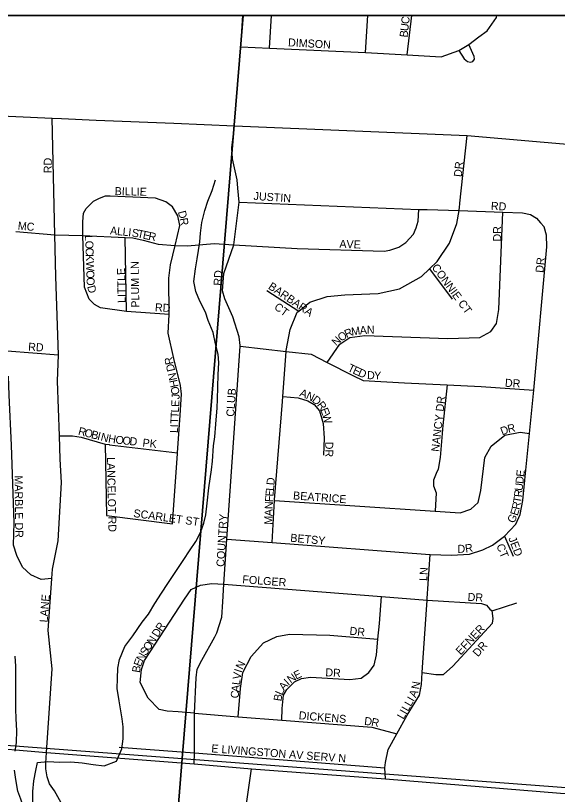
# Model space of a CAD drawing. Extents: x 0 to 34, y 0 to 22.
# Drawn here: x 7.208 to 7.849, y 19.979 to 20.9 of the extents above; entities that cross this region are included whole.
import ezdxf

# ---------------------------------------------------------------- set-up
doc = ezdxf.new("R2010")
doc.units = 0
for name, color, linetype in [('GM_X_City_Street', 7, 'Continuous'), ('GM_X_City_Street_Text', 7, 'Continuous'), ('GM_X_Minor_River', 7, 'Continuous'), ('GM_X_Section', 7, 'Continuous'), ('GM_X_Township', 7, 'Continuous'), ('GM_X_US_Route', 7, 'Continuous'), ('SH_Data', 7, 'Continuous')]:
    doc.layers.add(name, color=color, linetype=linetype)

msp = doc.modelspace()

# ---------------------------------------------------------------- linework, layer by layer
at = {"layer": 'GM_X_City_Street'}
for points in [[(7.46717, 20.77809), (7.47409, 20.86319), (7.47649, 20.9)], [(7.47409, 20.86319), (7.50811, 20.86148), (7.62155, 20.85632), (7.67071, 20.85357), (7.71131, 20.85115), (7.73218, 20.85867), (7.74375, 20.8656), (7.75568, 20.87493), (7.76558, 20.8821), (7.77658, 20.89792), (7.77707, 20.9)], [(7.50811, 20.86148), (7.5105, 20.9)], [(7.62155, 20.85632), (7.62451, 20.9)], [(7.67071, 20.85357), (7.67626, 20.9)], [(7.73218, 20.85867), (7.7385, 20.8487), (7.74222, 20.84559), (7.74598, 20.84475), (7.74866, 20.84583), (7.7506, 20.84845), (7.75028, 20.85149), (7.74375, 20.8656)], [(7.25731, 20.4677), (7.25821, 20.49881), (7.25521, 20.59154), (7.25388, 20.64062), (7.25079, 20.7786)], [(7.41893, 20.0151), (7.41918, 20.0279), (7.41909, 20.07484), (7.4212, 20.11671), (7.42251, 20.12695), (7.42798, 20.13751), (7.44322, 20.16538), (7.44556, 20.16991), (7.45155, 20.18843), (7.45261, 20.20665), (7.45404, 20.22751), (7.45769, 20.28074), (7.47337, 20.50912), (7.47342, 20.50989), (7.47207, 20.52017), (7.46449, 20.54384), (7.45497, 20.56489), (7.45247, 20.57443), (7.45393, 20.59492), (7.46582, 20.62889), (7.47201, 20.67928), (7.47146, 20.68771), (7.47059, 20.69583), (7.46972, 20.70569), (7.46741, 20.71642), (7.46421, 20.73063), (7.46334, 20.74369), (7.46649, 20.7697), (7.46717, 20.77809)], [(7.73323, 20.67817), (7.74188, 20.75814)], [(7.38932, 20.54657), (7.33877, 20.55007), (7.30811, 20.55427), (7.30108, 20.55825), (7.29453, 20.56458), (7.28925, 20.57898), (7.28705, 20.63994), (7.287, 20.65609), (7.28797, 20.66615), (7.29102, 20.67201), (7.29945, 20.67996)], [(7.38932, 20.54657), (7.38886, 20.58939), (7.39097, 20.60521), (7.39635, 20.62801), (7.40173, 20.65164), (7.39962, 20.66312), (7.39307, 20.67388), (7.38547, 20.67962), (7.37294, 20.68418), (7.31958, 20.68628), (7.31349, 20.68628), (7.30658, 20.68371), (7.29945, 20.67996)], [(7.28705, 20.63994), (7.33737, 20.63761), (7.34625, 20.63713), (7.35843, 20.63456), (7.37621, 20.62963), (7.39635, 20.62801), (7.41113, 20.62761), (7.4424, 20.63037), (7.46582, 20.62889), (7.54074, 20.62458), (7.64383, 20.62128), (7.65036, 20.62245), (7.66091, 20.62613), (7.66931, 20.63176), (7.67828, 20.64145), (7.68163, 20.6489), (7.68383, 20.65678), (7.6847, 20.67062)], [(7.47201, 20.67928), (7.6847, 20.67062), (7.69445, 20.67077), (7.73232, 20.66936), (7.7843, 20.66744), (7.80751, 20.66658), (7.81693, 20.66487), (7.82404, 20.66055), (7.82884, 20.65476)], [(7.51111, 20.27668), (7.51393, 20.32647), (7.51398, 20.32719), (7.52349, 20.44352), (7.52391, 20.44955), (7.52766, 20.50281), (7.52773, 20.50378), (7.53239, 20.52873), (7.54073, 20.54906), (7.54255, 20.5505), (7.55572, 20.5609), (7.57626, 20.56769), (7.59709, 20.56954), (7.63644, 20.57139), (7.66189, 20.57694), (7.68788, 20.59122), (7.69732, 20.60032), (7.70639, 20.60905), (7.72081, 20.63077), (7.72959, 20.65413), (7.73232, 20.66936), (7.73258, 20.67076), (7.73265, 20.67276), (7.73323, 20.67817)], [(7.57605, 20.48958), (7.59139, 20.51121), (7.60289, 20.51932), (7.6207, 20.52162), (7.71892, 20.51809), (7.75675, 20.51922), (7.76975, 20.52654), (7.77674, 20.53589), (7.77935, 20.55253), (7.7843, 20.66744)], [(7.78622, 20.28428), (7.79937, 20.29844), (7.80452, 20.31011), (7.80788, 20.32637), (7.81026, 20.35062), (7.81567, 20.40576), (7.82072, 20.45714), (7.83621, 20.62651), (7.83574, 20.64019), (7.83291, 20.65012), (7.82884, 20.65476)], [(7.20767, 20.64479), (7.25388, 20.64062), (7.28705, 20.63994)], [(7.33877, 20.55007), (7.33737, 20.63761)], [(7.69732, 20.60032), (7.72401, 20.56467)], [(7.50496, 20.57484), (7.54255, 20.5505)], [(7.39319, 20.29891), (7.39902, 20.38192), (7.39907, 20.38271), (7.4022, 20.4274), (7.40383, 20.45241), (7.40252, 20.46231), (7.39484, 20.49434), (7.38827, 20.52446), (7.38932, 20.54657)], [(7.04392, 20.49399), (7.06603, 20.5112), (7.07176, 20.51293), (7.08653, 20.51251), (7.19765, 20.50364), (7.25821, 20.49881)], [(7.47337, 20.50912), (7.52766, 20.50281), (7.55713, 20.49938), (7.57605, 20.48958), (7.60652, 20.47447), (7.61888, 20.46852), (7.66759, 20.46562), (7.71822, 20.46311), (7.7586, 20.46111), (7.82072, 20.45714)], [(7.25053, 20.23441), (7.23761, 20.23285), (7.22565, 20.23851), (7.21568, 20.24753), (7.20888, 20.2614), (7.20506, 20.27366), (7.20585, 20.30059), (7.2028, 20.39182), (7.20013, 20.45105), (7.19911, 20.47356)], [(7.24351, 20.01569), (7.24419, 20.02836), (7.25089, 20.12742), (7.24595, 20.17259), (7.25053, 20.23441), (7.25132, 20.24512), (7.2579, 20.27896), (7.26179, 20.34758), (7.26032, 20.37534), (7.25941, 20.40312), (7.25731, 20.4677)], [(7.71822, 20.46311), (7.71308, 20.41535), (7.71005, 20.37746), (7.7075, 20.36347), (7.70514, 20.35859), (7.70195, 20.35068), (7.70219, 20.34384), (7.70505, 20.33543), (7.70396, 20.31402)], [(7.52391, 20.44955), (7.54211, 20.44807), (7.55338, 20.44443), (7.56085, 20.4401), (7.56712, 20.43238), (7.57136, 20.41749), (7.57252, 20.40001), (7.57174, 20.37991)], [(7.51393, 20.32647), (7.70396, 20.31402), (7.73369, 20.31208), (7.74625, 20.31637), (7.7551, 20.32416), (7.75803, 20.33814), (7.76297, 20.37714), (7.77042, 20.39065), (7.78657, 20.40361), (7.80479, 20.40741), (7.81567, 20.40576)], [(7.25941, 20.40312), (7.27507, 20.40305), (7.28524, 20.40132), (7.31336, 20.39317), (7.31846, 20.39254), (7.31875, 20.3925)], [(7.31336, 20.39317), (7.31514, 20.30886)], [(7.31875, 20.3925), (7.39907, 20.38271)], [(7.31514, 20.30886), (7.39319, 20.29891)], [(7.45769, 20.28074), (7.51111, 20.27668), (7.69762, 20.26254), (7.69829, 20.26251), (7.72334, 20.26163), (7.74456, 20.2631), (7.76054, 20.26809), (7.77201, 20.27356), (7.78622, 20.28428)], [(7.78622, 20.28428), (7.79617, 20.2607)], [(7.64519, 19.99722), (7.64455, 20.01026), (7.64534, 20.01667), (7.64829, 20.03179), (7.65853, 20.05058), (7.67104, 20.0727), (7.6855, 20.09632), (7.68802, 20.1088), (7.68873, 20.12321), (7.6893, 20.13496), (7.69447, 20.20848), (7.6946, 20.21039), (7.69829, 20.26251)], [(7.41909, 20.07484), (7.40006, 20.07634), (7.38685, 20.07737), (7.37744, 20.07945), (7.36448, 20.09263), (7.35501, 20.11105), (7.35646, 20.12657), (7.36008, 20.13713), (7.40728, 20.20981), (7.41544, 20.22103), (7.42651, 20.2265), (7.43978, 20.22812), (7.45404, 20.22751)], [(7.45404, 20.22751), (7.64059, 20.21301), (7.69447, 20.20848), (7.75875, 20.20452), (7.76476, 20.2025), (7.76882, 20.19786), (7.77143, 20.19592), (7.80073, 20.20557)], [(7.52271, 20.06672), (7.52301, 20.08066), (7.52445, 20.09619), (7.52837, 20.10295), (7.53763, 20.11187), (7.54602, 20.11587), (7.55664, 20.11755), (7.60308, 20.11471), (7.61635, 20.11633), (7.62556, 20.12298), (7.63178, 20.13158), (7.63467, 20.14405), (7.63636, 20.16258), (7.63807, 20.18118), (7.64059, 20.21301)], [(7.68873, 20.12321), (7.70489, 20.1206), (7.71397, 20.12079), (7.72513, 20.13043), (7.7719, 20.18148), (7.77276, 20.18678), (7.77143, 20.19592)], [(7.47105, 20.07077), (7.47358, 20.10407), (7.47661, 20.12298), (7.48644, 20.14214), (7.50075, 20.15817), (7.51679, 20.16581), (7.53158, 20.16855), (7.57956, 20.16719), (7.63636, 20.16258)], [(7.41909, 20.07484), (7.47105, 20.07077), (7.52271, 20.06672), (7.62917, 20.05837), (7.63669, 20.05632), (7.65853, 20.05058)], [(6.90291, 20.05472), (6.90291, 20.05472), (7.16116, 20.03551), (7.24419, 20.02836), (7.41893, 20.0151), (7.48652, 20.0093)], [(7.33005, 20.03487), (7.41918, 20.0279), (7.64455, 20.01026)], [(7.12805, 19.5971), (7.12788, 19.60303), (7.13529, 19.62004), (7.14308, 19.63744), (7.15701, 19.66048), (7.18874, 19.71372), (7.21392, 19.75791), (7.22441, 19.77908), (7.23406, 19.79341), (7.23776, 19.8047), (7.23878, 19.8078), (7.24239, 19.82525), (7.24469, 19.86056), (7.25022, 19.91334), (7.26132, 19.96893), (7.25357, 19.98307), (7.24776, 19.99142), (7.24479, 19.99976), (7.24315, 20.00899), (7.24351, 20.01569)], [(7.47554, 19.93176), (7.48652, 20.0093)], [(7.48652, 20.0093), (7.64519, 19.99722), (7.8522, 19.98043), (8.03575, 19.96709), (8.08374, 19.96342)]]:
    msp.add_lwpolyline(points, dxfattribs=at)
at = {"layer": 'GM_X_Minor_River'}
for points in [[(7.43161, 20.66966), (7.43509, 20.68065), (7.44008, 20.69314), (7.44394, 20.70564)], [(7.22799, 19.963), (7.22811, 19.98236), (7.22932, 19.99488), (7.23166, 20.00702), (7.23361, 20.01649), (7.24572, 20.01794), (7.2597, 20.0171), (7.27294, 20.01739), (7.28617, 20.01617), (7.29939, 20.0142), (7.31224, 20.0126), (7.32702, 20.0182), (7.33316, 20.03259), (7.33475, 20.04473), (7.33484, 20.05877), (7.33376, 20.06827), (7.33156, 20.08005), (7.33011, 20.08955), (7.32793, 20.10399), (7.328, 20.11613), (7.32846, 20.12828), (7.33041, 20.13852), (7.33693, 20.15366), (7.34646, 20.16651), (7.35715, 20.18239), (7.36477, 20.19221), (7.37241, 20.20469), (7.38005, 20.21679), (7.38769, 20.22851), (7.39799, 20.24363), (7.40677, 20.25686), (7.41326, 20.26707), (7.42089, 20.27803), (7.42625, 20.28863), (7.4301, 20.29961), (7.4328, 20.30946), (7.4344, 20.3235), (7.43603, 20.34133), (7.43956, 20.36256), (7.44038, 20.37318), (7.44163, 20.39102), (7.4432, 20.40163), (7.44443, 20.41681), (7.44606, 20.43616), (7.4465, 20.4464), (7.44697, 20.46044), (7.44744, 20.47562), (7.4479, 20.48928), (7.44721, 20.49953), (7.44426, 20.5117), (7.44131, 20.525), (7.43535, 20.53946), (7.43239, 20.54934), (7.42566, 20.56229), (7.42081, 20.5737), (7.41862, 20.58548), (7.4206, 20.60065), (7.42257, 20.61241), (7.42414, 20.62227), (7.42571, 20.6325), (7.42653, 20.64274), (7.42812, 20.65526), (7.43161, 20.66966)], [(7.20722, 20.02994), (7.20842, 20.04018), (7.20889, 20.05461), (7.20821, 20.06827), (7.20791, 20.08005), (7.20797, 20.08991), (7.20766, 20.10168), (7.20774, 20.11383), (7.20784, 20.13053), (7.20716, 20.14231)], [(7.22822, 19.94989), (7.22035, 19.95128), (7.21702, 19.96345), (7.21368, 19.97334), (7.21034, 19.98285), (7.20777, 19.99653), (7.20633, 20.00755)]]:
    msp.add_lwpolyline(points, dxfattribs=at)
at = {"layer": 'GM_X_Section'}
for p, q in [((7.47668, 20.9), (6.96615, 20.9)), ((7.98444, 20.9), (7.47668, 20.9))]:
    msp.add_line(p, q, dxfattribs=at)
for points in [[(6.96615, 20.9), (6.89954, 20.05948), (7.40469, 20.02134), (7.47668, 20.9)], [(7.47668, 20.9), (7.40469, 20.02134), (7.91105, 19.98299), (7.98444, 20.9)]]:
    msp.add_lwpolyline(points, dxfattribs=at)
for points in [[(6.89954, 20.05948), (7.40469, 20.02134), (7.32396, 19.01244), (6.82179, 19.05189)], [(7.40469, 20.02134), (7.91105, 19.98299), (7.83199, 18.97493), (7.32396, 19.01244)]]:
    msp.add_lwpolyline(points, close=True, dxfattribs=at)
at = {"layer": 'GM_X_Township'}
msp.add_lwpolyline([(9.4, 17.82945), (9.4, 20.9), (4.42993, 20.9)], dxfattribs=at)
at = {"layer": 'GM_X_US_Route'}
for points in [[(6.95519, 20.7898), (7.05834, 20.78049), (7.15585, 20.78303), (7.25079, 20.7786), (7.26185, 20.77814)], [(7.26185, 20.77814), (7.30278, 20.77645)], [(7.30278, 20.77645), (7.39487, 20.77266)], [(7.39487, 20.77266), (7.46649, 20.7697), (7.74188, 20.75814), (7.87401, 20.74661), (7.96446, 20.74516), (8.13798, 20.74238), (8.24345, 20.73449)]]:
    msp.add_lwpolyline(points, dxfattribs=at)
at = {"layer": 'SH_Data'}
msp.add_line((2.6, 20.9), (9.4, 20.9), dxfattribs=at)

# ---------------------------------------------------------------- texts
at = {"layer": 'GM_X_City_Street_Text'}
for s, height, rotation, p in [('C', 0.00947, 83.50034, (7.673, 20.8895)), ('U', 0.00947, 83.49143, (7.67205, 20.88121)), ('B', 0.00947, 83.50156, (7.6712, 20.87376)), ('DIMSON', 0.00947, 356.8796, (7.52974, 20.86367)), ('RD', 0.00947, 90, (7.25037, 20.71356)), ('DR', 0.00947, 83.982, (7.73541, 20.70875)), ('BILLIE', 0.00947, 358.69884, (7.32469, 20.68772)), ('JUSTIN', 0.00947, 356.26572, (7.48893, 20.68201)), ('RD', 0.00947, 356.82219, (7.76975, 20.67034)), ('D', 0.00947, 285.64815, (7.39944, 20.66777)), ('MC', 0.00947, 354.79841, (7.20981, 20.647)), ('R', 0.00947, 279.638, (7.40163, 20.66)), ('A', 0.00947, 354.72443, (7.31897, 20.64117)), ('L', 0.00947, 354.73277, (7.32727, 20.64041)), ('L', 0.00947, 354.75743, (7.33391, 20.63979)), ('I', 0.00947, 353.95437, (7.34052, 20.63919)), ('S', 0.00947, 350.64099, (7.34451, 20.63877)), ('T', 0.00947, 348.19717, (7.35099, 20.6377)), ('E', 0.00947, 348.03116, (7.35751, 20.63634)), ('R', 0.00947, 348.04025, (7.36403, 20.63496)), ('DR', 0.00947, 90, (7.78204, 20.63273)), ('L', 0.00947, 271.8855, (7.28976, 20.64026)), ('AVE', 0.00947, 358.0261, (7.59054, 20.62534)), ('O', 0.00947, 271.90891, (7.28998, 20.6336)), ('C', 0.00947, 271.87032, (7.29026, 20.62527)), ('K', 0.00947, 271.90891, (7.29051, 20.61777)), ('W', 0.00947, 271.88339, (7.29078, 20.60944)), ('PLUM LN', 0.00947, 90.93868, (7.35398, 20.55463)), ('DR', 0.00947, 83.99458, (7.83204, 20.59541)), ('O', 0.00947, 271.88003, (7.29114, 20.59861)), ('LITTLE', 0.00947, 91.21819, (7.33787, 20.56019)), ('RD', 0.00947, 86.81007, (7.4512, 20.58033)), ('CONNIE CT', 0.00947, 306.25242, (7.69942, 20.60211)), ('O', 0.00947, 271.90891, (7.29141, 20.59028)), ('D', 0.00947, 285.65736, (7.29207, 20.5795)), ('BARBARA', 0.00947, 325.83878, (7.50565, 20.57754)), ('RD', 0.00947, 356.98902, (7.37224, 20.55034)), ('CT', 0.00947, 323.74111, (7.51273, 20.55353)), ('A', 0.00947, 5.01235, (7.61515, 20.52291)), ('N', 0.00947, 0.30604, (7.62325, 20.52363)), ('O', 0.00947, 34.29016, (7.59273, 20.51409)), ('R', 0.00947, 24.19674, (7.59923, 20.51857)), ('M', 0.00947, 8.51906, (7.60541, 20.52145)), ('N', 0.00947, 44.64451, (7.58715, 20.50852)), ('RD', 0.00947, 356.98902, (7.22224, 20.50368)), ('R', 0.00947, 102.38811, (7.39456, 20.48815)), ('D', 0.00947, 102.37712, (7.39634, 20.48001)), ('T', 0.00947, 334.97485, (7.59962, 20.48002)), ('N', 0.00947, 102.37122, (7.39867, 20.46942)), ('E', 0.00947, 335.00291, (7.60566, 20.4772)), ('D', 0.00947, 336.13625, (7.61189, 20.4743)), ('D', 0.00947, 358.07959, (7.62328, 20.47007)), ('Y', 0.00947, 358.0326, (7.63161, 20.46979)), ('H', 0.00947, 102.10636, (7.40043, 20.46123)), ('DR', 0.00947, 356.97755, (7.7864, 20.46106)), ('O', 0.00947, 97.54334, (7.40166, 20.45216)), ('J', 0.00947, 87.14007, (7.40153, 20.44612)), ('CLUB', 0.00947, 86.34954, (7.4662, 20.42534)), ('A', 0.00947, 338.39749, (7.54276, 20.45023)), ('N', 0.00947, 334.90125, (7.55037, 20.44723)), ('D', 0.00947, 321.97167, (7.55744, 20.44399)), ('NANCY DR', 0.00947, 83.66047, (7.70871, 20.38376)), ('E', 0.00947, 87.1368, (7.40107, 20.43697)), ('R', 0.00947, 308.40953, (7.56358, 20.43927)), ('T', 0.00947, 87.15084, (7.40041, 20.42365)), ('L', 0.00947, 87.13077, (7.40074, 20.43031)), ('E', 0.00947, 290.95904, (7.56787, 20.43405)), ('T', 0.00947, 87.13077, (7.40007, 20.41699)), ('W', 0.00947, 285.05164, (7.57017, 20.42807)), ('R', 0.00947, 345.43942, (7.28093, 20.40445)), ('L', 0.00947, 87.13077, (7.39953, 20.40616)), ('I', 0.00947, 87.14007, (7.39987, 20.41283)), ('D', 0.00947, 21.03437, (7.78335, 20.40342)), ('R', 0.00947, 13.02919, (7.79079, 20.40631)), ('O', 0.00947, 345.41838, (7.28819, 20.40257)), ('B', 0.00947, 345.44297, (7.29626, 20.40047)), ('I', 0.00947, 345.46555, (7.30352, 20.39858)), ('N', 0.00947, 345.41775, (7.30755, 20.39754)), ('H', 0.00947, 350.98994, (7.3166, 20.39523)), ('O', 0.00947, 354.09061, (7.32538, 20.39385)), ('O', 0.00947, 354.14594, (7.33369, 20.39299)), ('D', 0.00947, 354.13284, (7.34197, 20.39215)), ('PK', 0.00947, 353.66247, (7.35735, 20.39033)), ('DR', 0.00947, 270, (7.57393, 20.39606)), ('LANCELOT RD', 0.0094697, 271.19516, (7.3156, 20.37776)), ('E', 0.00947, 83.81367, (7.80923, 20.35409)), ('MARBLE DR', 0.00947, 270.6919, (7.20631, 20.3561)), ('D', 0.00947, 84.80048, (7.51371, 20.34421)), ('D', 0.00947, 83.80744, (7.80833, 20.34581)), ('E', 0.00947, 84.91192, (7.51251, 20.33093)), ('L', 0.00947, 84.80309, (7.5131, 20.33757)), ('R', 0.00947, 83.69177, (7.8066, 20.33005)), ('U', 0.00947, 83.78499, (7.80743, 20.33752)), ('F', 0.00947, 86.08958, (7.51206, 20.32434)), ('BEATRICE', 0.00947, 355.79356, (7.53561, 20.32784)), ('T', 0.00947, 80.36718, (7.8054, 20.32288)), ('N', 0.00947, 88.05444, (7.51178, 20.31609)), ('R', 0.00947, 78.09189, (7.80378, 20.31513)), ('SCARLET ST', 0.00947, 352.16962, (7.34656, 20.30699)), ('A', 0.00947, 88.2729, (7.51153, 20.30777)), ('E', 0.00947, 72.92909, (7.80159, 20.30786)), ('COUNTRY', 0.00947, 86.63127, (7.45453, 20.2478)), ('M', 0.00947, 88.28746, (7.51123, 20.29778)), ('G', 0.00947, 63.21988, (7.79718, 20.2988)), ('BETSY', 0.00947, 354.80333, (7.53231, 20.27784)), ('R', 0.00947, 8.7032, (7.74013, 20.26486)), ('CT', 0.00947, 292.38208, (7.77623, 20.27304)), ('JED', 0.00947, 291.37421, (7.79047, 20.28171)), ('D', 0.00947, 1.6397, (7.73055, 20.26451)), ('FOLGER', 0.00947, 355.76599, (7.47561, 20.22867)), ('LN', 0.00947, 86.97755, (7.69457, 20.23115)), ('LANE', 0.00947, 85.36691, (7.24537, 20.18204)), ('DR', 0.00947, 356.98902, (7.74224, 20.20784)), ('D', 0.00947, 57.10621, (7.37586, 20.16395)), ('R', 0.00947, 57.09115, (7.38039, 20.17095)), ('DR', 0.00947, 353.99459, (7.60233, 20.16783)), ('EFNER', 0.00947, 46.84306, (7.73421, 20.14309)), ('N', 0.00947, 57.09076, (7.36998, 20.15485)), ('O', 0.00947, 57.09799, (7.36545, 20.14786)), ('DR', 0.00947, 49.40513, (7.7547, 20.1409)), ('N', 0.00947, 60.92204, (7.35792, 20.13509)), ('S', 0.00947, 57.64408, (7.3619, 20.14225)), ('E', 0.00947, 67.89925, (7.35554, 20.12919)), ('N', 0.00947, 64.00191, (7.47596, 20.12583)), ('B', 0.00947, 80.82914, (7.3545, 20.12233)), ('I', 0.00947, 71.91061, (7.4748, 20.12219)), ('DR', 0.00947, 356.98902, (7.5739, 20.11864)), ('V', 0.00947, 81.61948, (7.47368, 20.11436)), ('N', 0.00947, 36.21859, (7.53317, 20.10979)), ('E', 0.00947, 26.13748, (7.53952, 20.11449)), ('L', 0.00947, 83.6625, (7.47296, 20.10782)), ('A', 0.00947, 50.26158, (7.52523, 20.10098)), ('I', 0.00947, 42.58831, (7.53032, 20.10715)), ('N', 0.00947, 80.64922, (7.68502, 20.10269)), ('C', 0.00947, 83.67321, (7.47121, 20.09208)), ('A', 0.00947, 83.64773, (7.47204, 20.09953)), ('L', 0.00947, 66.7476, (7.52297, 20.09547)), ('A', 0.00947, 66.87059, (7.68106, 20.09264)), ('B', 0.00947, 81.73939, (7.52207, 20.08867)), ('I', 0.00947, 60.26596, (7.67846, 20.08796)), ('L', 0.00947, 60.30058, (7.67186, 20.07638)), ('L', 0.00947, 60.30593, (7.67516, 20.08217)), ('DICKENS', 0.00947, 355.23515, (7.5423, 20.06784)), ('L', 0.00947, 60.2924, (7.66648, 20.06697)), ('I', 0.00947, 60.26596, (7.66979, 20.07275)), ('D', 0.00947, 353.66946, (7.61976, 20.06117)), ('R', 0.00947, 348.43284, (7.62781, 20.06029)), ('E LIVINGSTON AV SERV N', 0.0094697, 355.67758, (7.43895, 20.02867))]:
    msp.add_text(s, height=height, rotation=rotation, dxfattribs=at).set_placement(p)

doc.saveas('drawing.dxf')
